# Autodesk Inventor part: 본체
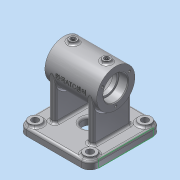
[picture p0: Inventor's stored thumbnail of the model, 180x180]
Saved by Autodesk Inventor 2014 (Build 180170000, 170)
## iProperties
Created: 2025-10
Part Number: 본체
Material: 알루미늄 6061
Document SubType Name: Modeling
Designer: dg
Density: 2.71 g/cm^3
Appearance: 알루미늄 - 평지
Mass: 505.532 g
Surface Area: 499.638 cm^2
Volume: 186.543 cm^3
Author: dg
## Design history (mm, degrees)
sketch "스케치1"
  geometry: L1 (-47, -47)-(47, -47); L2 (47, -47)-(47, 47); L3 (47, 47)-(-47, 47); L4 (-47, 47)-(-47, -47); L5 (-47, -47)-(47, 47); L6 (47, -47)-(-47, 47); 1 further point
  constraints: 12 end point, 2 midpoint, 2 parallel, 1 horizontal, 1 perpendicular
  dimensions: "d0" = 94 distance of L1.end L2.end; "d1" = 94 distance of L1.start L1.end
extrude "돌출1" new body sketch "스케치1" distance "d2" = 10; taper "d3" = 0 deg
sketch "스케치2"
  geometry: L1 (0, 47)-(0, -47) reference; L2 (66, -49.804)-(66, 56.223); L3 (66, 33.854)-(91, 33.854); L4 (91, 33.854)-(91, -34.146); L5 (91, -34.146)-(66, -34.146); L6 (82, 33.854)-(82, 21.854); L7 (82, 21.854)-(79.5, 21.854); L8 (79.5, 21.854)-(79.5, 16.258); L9 (79.5, 16.258)-(86, 5); L10 (86, 5)-(86, -5); L11 (86, -5)-(79.5, -16.258); L12 (79.5, -16.258)-(79.5, -22.146); L13 (79.5, -22.146)-(82, -22.146); L14 (82, -22.146)-(82, -34.146); 3 further points
  constraints: 26 end point, 6 parallel, 5 perpendicular, 4 point on line, 2 midpoint, 1 horizontal alignment
  dimensions: "d5" = 68 distance of L3.end L4.end; "d6" = 50 diameter of L4 L2; "d7" = 12 distance of L6.start L6.end; "d8" = 12 distance of L13.end L14.end; "d9" = 30 deg angle of L8 L9; "d10" = 30 deg angle of L12 L11; "d11" = 10 distance of L9.end L10.end; "d49" = 32 diameter of L6 L2; "d50" = 27 diameter of L8 L2; "d51" = 32 diameter of L14 L2; "d53" = 27 diameter of L12 L2; "d54" = 40 diameter of L10 L2; "d58" = 66 horizontal distance of L1.end L2.start
revolve "회전1" sketch "스케치2" stored, may be unused: angle "d12" = 90 deg
sketch "스케치3"
  geometry: L1 (-47, 47)-(-47, -47) reference; L2 (47, -47)-(47, 47) reference; L3 (-25, -29)-(25, -29); L4 (25, -29)-(25, -21); L5 (25, -21)-(-25, -21); L6 (-25, -21)-(-25, -29); L7 (-47, 0)-(47, 0); L8 (-25, 29)-(25, 29); L9 (25, 29)-(25, 21); L10 (25, 21)-(-25, 21); L11 (-25, 21)-(-25, 29); 4 further points
  constraints: 18 end point, 5 symmetric about line, 4 midpoint, 2 parallel, 1 horizontal, 1 perpendicular, 1 vertical alignment
  dimensions: "d13" = 8 distance of L5.end L3.start; "d14" = 50 distance of L3.start L3.end; "d15" = 21 distance between parallel lines of L7 L5
extrude "돌출2" join sketch "스케치3" stored distance "d16" = 10; taper "d17" = 0 deg
fillet "모깎기1" dims "d18" = 11
sketch "스케치4"
  geometry: C1 r 8 at (-36, -36); C2 r 8 at (36, -36); C3 r 8 at (36, 36); C4 r 8 at (-36, 36); A1 r 11 centre (-36, 36) between (-36, 47) and (-47, 36) reference; A2 r 11 centre (-36, -36) between (-47, -36) and (-36, -47) reference; A3 r 11 centre (36, -36) between (36, -47) and (47, -36) reference; A4 r 11 centre (36, 36) between (47, 36) and (36, 47) reference; 1 further point
  constraints: 4 centre point, 4 coincident
  dimensions: "d19" = 16 diameter of C1; "d20" = 16 diameter of C2; "d21" = 16 diameter of C3; "d22" = 16 diameter of C4
extrude "돌출3" join sketch "스케치4" distance "d23" = 3; taper "d24" = 0 deg
hole "구멍1" diameter "d27" = 9; stored, may be unused: countersink angle "d31" = 90 deg, drill point angle "d33" = 118 deg; dims "d25" = 10, "d26" = 10, "d28" = 6, "d29" = 4, "d30" = 2, "d32" = 8
sketch "스케치5"
  geometry: C1 r 16 at (0, 0) reference; 2 further points
hole "구멍2" sketch "스케치5" at (0, -20.5) diameter "d41" = 3.242; stored, may be unused: countersink angle "d45" = 90 deg, drill point angle "d47" = 118 deg; dims "d42" = 8, "d43" = 4, "d44" = 2, "d46" = 10
sketch "스케치6"
  geometry: L1 (0, 0)-(0, 10) reference; L2 (0, 0)-(72, 0) reference; L3 (72, 10)-(72, 0) reference; L4 (0, 10)-(72, 10) reference; 1 further point
node "작업 평면1"
sketch "스케치7"
  geometry: L1 (-25, 33.854)-(25, 33.854) reference; L2 (0, 33.854)-(0, 21.854); C1 r 5 at (0, 21.854); 1 further point
  constraints: 2 end point, 1 centre point, 1 coincident, 1 midpoint, 1 perpendicular
  dimensions: "d60" = 12 distance of L2.start L2.end; "d61" = 10 diameter of C1
extrude "돌출4" join sketch "스케치7" stored distance "d62" = 3; taper "d63" = 0 deg
sketch "스케치8"
  geometry: C1 r 5 at (0, 0) reference; C2 r 3.3 at (0, 0); 1 further point
  constraints: 1 centre point, 1 coincident
  dimensions: "d64" = 6.6 diameter of C2
extrude "돌출5" cut sketch "스케치8" distance "d65" = 2; taper "d66" = 0 deg
sketch "스케치9"
  geometry: C1 r 3.3 at (0, 0) reference; 2 further points
  constraints: 1 coincident
hole "구멍3" sketch "스케치9" at (0, 0) diameter "d67" = 5.188; stored, may be unused: countersink angle "d71" = 90 deg, drill point angle "d73" = 118 deg; dims "d68" = 15, "d69" = 4, "d70" = 2, "d72" = 17
node "작업 평면2"
sketch "스케치10"
  geometry: C1 r 6 at (0, 0); 1 further point
  constraints: 1 centre point, 1 coincident
  dimensions: "d75" = 12 diameter of C1
extrude "돌출6" join sketch "스케치10" stored distance "d76" = 2; taper "d77" = 0 deg
sketch "스케치11"
  geometry: C1 r 6 at (0, 0) reference; 1 further point
  constraints: 1 coincident
hole "구멍4" sketch "스케치11" at (0, 0) diameter "d78" = 5.188; stored, may be unused: countersink angle "d82" = 90 deg, drill point angle "d84" = 118 deg; dims "d79" = 20, "d80" = 4, "d81" = 2, "d83" = 10
sketch "스케치12"
  geometry: C1 r 10 at (0, 0); 1 further point
  constraints: 1 centre point, 1 coincident
  dimensions: "d85" = 20 diameter of C1
extrude "돌출7" cut sketch "스케치12" stored distance "d86" = 2; taper "d87" = 0 deg
fillet "모깎기2" dims "d88" = 0.3
chamfer "모따기1" distance "d89" = 1; stored, may be unused: second distance "d90" = 2, angle "d91" = 45 deg
fillet "모깎기3" dims "d92" = 3
fillet "모깎기4" dims "d93" = 3
fillet "모깎기5" dims "d94" = 3
fillet "모깎기6" dims "d95" = 3
fillet "모깎기7" dims "d96" = 3
fillet "모깎기8" dims "d97" = 3
node "작업 평면3"
sketch "스케치13"
  geometry: L1 (66, -35.854)-(66, 36.146) reference; 3 further points
  constraints: 1 horizontal alignment, 1 midpoint, 1 other
  dimensions: "d98" = 66 distance from line of point (0, 0.146) L1
feature "엠보싱1" sketch "스케치13" dims "d5" = 68, "d6" = 50, "d7" = 12, "d8" = 12, "d9" = 30 deg, "d10" = 30 deg, "d11" = 10, "d49" = 32, "d50" = 27, "d51" = 32, "d53" = 27, "d54" = 40, "d58" = 66, "d99" = 0.5, "d100" = 0
sketch "스케치14"
  geometry: L1 (-25, -34.146)-(25, -34.146) reference; L2 (0, -34.146)-(0, -22.146); C1 r 5 at (0, -22.146); 1 further point
  constraints: 2 end point, 1 centre point, 1 coincident, 1 midpoint, 1 perpendicular
  dimensions: "d101" = 12 distance of L2.start L2.end; "d102" = 10 diameter of C1
extrude "돌출8" join sketch "스케치14" stored distance "d103" = 2; taper "d104" = 0 deg
sketch "스케치15"
  geometry: C1 r 5 at (0, 0) reference; C2 r 3.3 at (0, 0); 1 further point
  constraints: 1 centre point, 1 coincident
  dimensions: "d105" = 6.6 diameter of C2
extrude "돌출9" cut sketch "스케치15" distance "d106" = 2; taper "d107" = 0 deg
sketch "스케치16"
  geometry: C1 r 3.3 at (0, 0) reference; 2 further points
  constraints: 1 coincident
hole "구멍5" sketch "스케치16" at (0, 0) diameter "d108" = 5.188; stored, may be unused: countersink angle "d112" = 90 deg, drill point angle "d114" = 118 deg; dims "d109" = 15, "d110" = 4, "d111" = 2, "d113" = 17
sketch "스케치17"
  geometry: 2 further points
hole "구멍6" sketch "스케치17" at (0, -20.5) diameter "d116" = 3.242; stored, may be unused: countersink angle "d120" = 90 deg, drill point angle "d122" = 118 deg; dims "d117" = 8, "d118" = 4, "d119" = 2, "d121" = 10
fillet "모깎기9" dims "d126" = 3
node "솔리드1"
pattern_linear "직사각형 패턴1" dims "d36" = 72, "d39" = 72
pattern_circular "원형 패턴1" dims angle "d56" = 360 deg
pattern_circular "원형 패턴2" dims angle "d124" = 360 deg
other parameters: "d59" = -94, "d74" = -38
